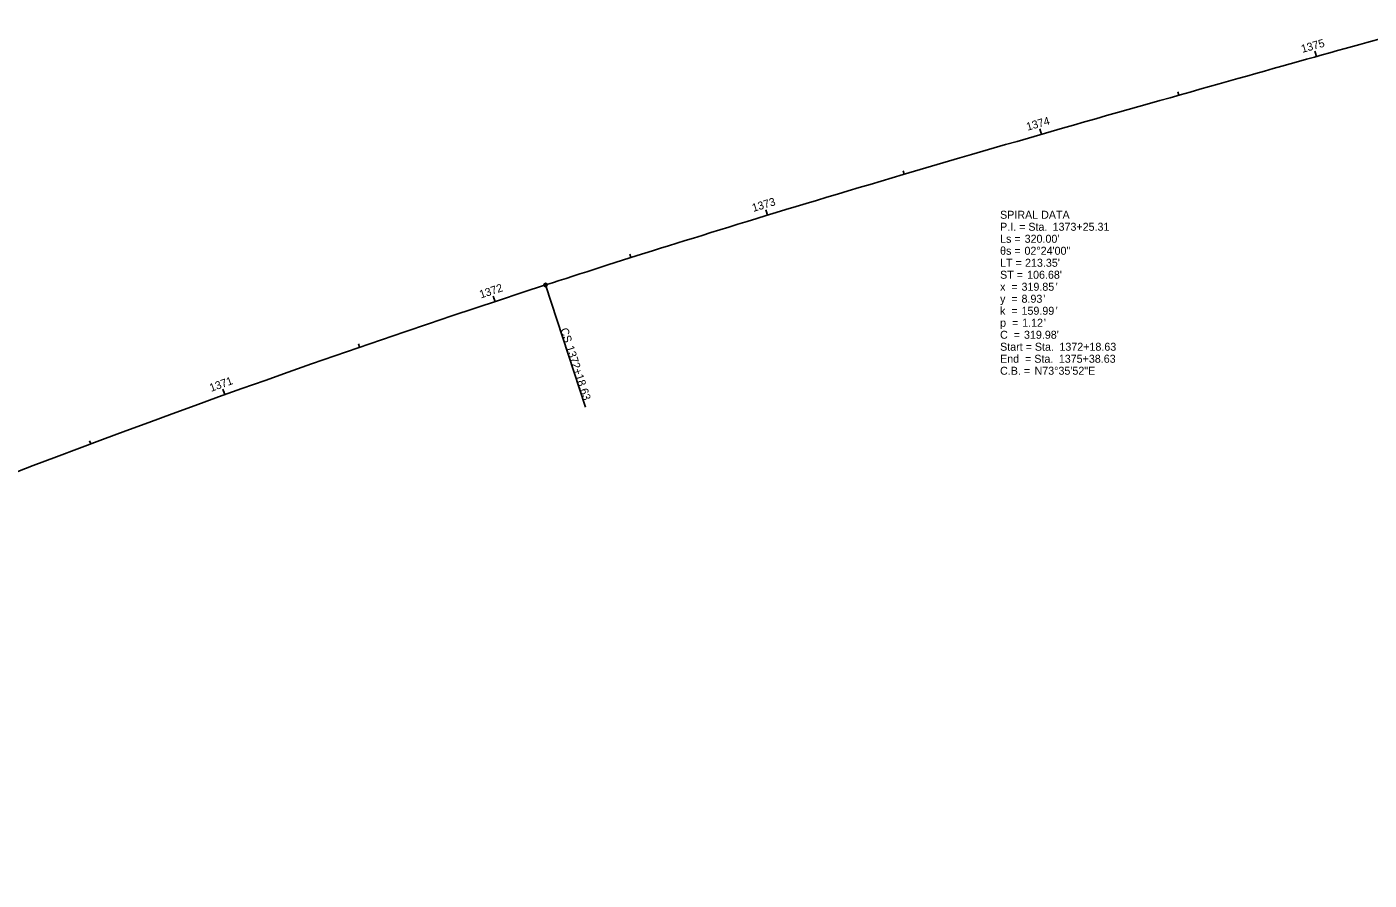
# Model space of a CAD drawing. Extents: x 153500 to 156291, y 370917 to 372075.
# Drawn here: x 154876 to 155345.7, y 371473.6 to 371772.3 of the extents above; entities that cross this region are included whole.
import ezdxf

# ---------------------------------------------------------------- set-up
doc = ezdxf.new("R2010")
doc.units = 0
for name, color, linetype in [('Default', 7, 'Continuous'), ('GE_X_Alignment', 7, 'Continuous'), ('GE_X_Alignment_1000_Curve_Data', 7, 'Continuous'), ('GE_X_Alignment_1000_Stations', 7, 'Continuous'), ('GE_X_Alignment_100_Curve_Data', 7, 'Continuous'), ('GE_X_Alignment_100_Stations', 7, 'Continuous'), ('GE_X_Alignment_500_Curve_Data', 7, 'Continuous'), ('GE_X_Alignment_500_Stations', 7, 'Continuous')]:
    doc.layers.add(name, color=color, linetype=linetype)

msp = doc.modelspace()

# ---------------------------------------------------------------- linework, layer by layer
at = {"layer": 'Default'}
msp.add_arc((156238, 368049.26), 3819.72, 108.0022, 116.29803, dxfattribs=at)
msp.add_open_spline([(155057.5, 371681.99), (155070.18, 371686.11), (155095.59, 371694.22), (155146.54, 371709.97), (155210.47, 371728.9), (155274.58, 371747.17), (155325.93, 371761.58), (155351.61, 371768.75), (155364.46, 371772.34)], degree=3, dxfattribs=at)
at = {"layer": 'GE_X_Alignment'}
msp.add_arc((156238, 368049.26), 3819.72, 108.0022, 116.29803, dxfattribs=at)
msp.add_open_spline([(155057.5, 371681.99), (155070.18, 371686.11), (155095.59, 371694.22), (155146.54, 371709.97), (155210.47, 371728.9), (155274.58, 371747.17), (155325.93, 371761.58), (155351.61, 371768.75), (155364.46, 371772.34)], degree=3, dxfattribs=at)
at = {"layer": 'GE_X_Alignment_1000_Stations'}
for p, q in [((155327.26, 371761.94), (155326.93, 371763.1)), ((155057.5, 371681.99), (155071.41, 371639.19))]:
    msp.add_line(p, q, dxfattribs=at)
msp.add_circle((155057.5, 371681.99), 0.6, dxfattribs=at)
at = {"layer": 'GE_X_Alignment_100_Stations'}
for p, q in [((155327.26, 371761.94), (155326.72, 371763.87)), ((155279.12, 371748.41), (155278.8, 371749.57)), ((155231.04, 371734.71), (155230.48, 371736.63)), ((155183.03, 371720.73), (155182.69, 371721.88)), ((155135.13, 371706.38), (155134.55, 371708.29)), ((155087.38, 371691.56), (155087.02, 371692.71)), ((155057.5, 371681.99), (155071.41, 371639.19)), ((155039.8, 371676.19), (155039.18, 371678.09)), ((154992.43, 371660.19), (154992.04, 371661.33)), ((154945.27, 371643.58), (154944.6, 371645.46)), ((154898.33, 371626.35), (154897.91, 371627.47))]:
    msp.add_line(p, q, dxfattribs=at)
msp.add_circle((155057.5, 371681.99), 0.6, dxfattribs=at)
at = {"layer": 'GE_X_Alignment_500_Stations'}
for p, q in [((155327.26, 371761.94), (155326.72, 371763.87)), ((155231.04, 371734.71), (155230.71, 371735.86)), ((155135.13, 371706.38), (155134.78, 371707.53)), ((155057.5, 371681.99), (155071.41, 371639.19)), ((155039.8, 371676.19), (155039.43, 371677.33)), ((154945.27, 371643.58), (154944.87, 371644.71))]:
    msp.add_line(p, q, dxfattribs=at)
msp.add_circle((155057.5, 371681.99), 0.6, dxfattribs=at)

# ---------------------------------------------------------------- texts
at = {"layer": 'GE_X_Alignment_1000_Curve_Data'}
for s, p in [('SPIRAL DATA', (155216.56, 371705.16)), ('P.I. = Sta. ', (155216.56, 371700.96)), ('1373+25.31', (155234.93, 371700.96)), ('Ls = ', (155216.56, 371696.76)), ("320.00'", (155225.15, 371696.76)), ('θs = ', (155216.56, 371692.56)), ('02°24\'00"', (155225.09, 371692.56)), ('LT = ', (155216.56, 371688.36)), ("213.35'", (155225.29, 371688.36)), ('ST = ', (155216.56, 371684.16)), ("106.68'", (155226.02, 371684.16)), ('x  = ', (155216.56, 371679.96)), ('319.85', (155224.06, 371679.96)), ("'", (155236.02, 371679.96)), ('y  = ', (155216.56, 371675.76)), ('k  = ', (155216.56, 371671.56)), ('8.93', (155224.06, 371675.76)), ('159.99', (155224.06, 371671.56)), ("'", (155231.67, 371675.76)), ("'", (155236.02, 371671.56)), ('p  = ', (155216.56, 371667.36)), ('1.12', (155224.28, 371667.36)), ("'", (155231.89, 371667.36)), ('C  = ', (155216.56, 371663.16)), ("319.98'", (155224.93, 371663.16)), ('Start = Sta. ', (155216.56, 371658.96)), ('1372+18.63', (155237.32, 371658.96)), ('End  = Sta. ', (155216.56, 371654.76)), ('1375+38.63', (155237.11, 371654.76)), ('C.B. = ', (155216.56, 371650.56)), ('N73°35\'52"E', (155228.62, 371650.56))]:
    msp.add_text(s, height=2.8, dxfattribs=at).set_placement(p)
at = {"layer": 'GE_X_Alignment_1000_Stations'}
for s, p in [('CS', (155062.6, 371666.45)), ('1372+18.63', (155064.62, 371660.25))]:
    msp.add_text(s, height=2.8, rotation=288.0022, dxfattribs=at).set_placement(p)
at = {"layer": 'GE_X_Alignment_100_Curve_Data'}
for s, p in [('SPIRAL DATA', (155216.56, 371705.16)), ('P.I. = Sta. ', (155216.56, 371700.96)), ('1373+25.31', (155234.93, 371700.96)), ('Ls = ', (155216.56, 371696.76)), ("320.00'", (155225.15, 371696.76)), ('θs = ', (155216.56, 371692.56)), ('02°24\'00"', (155225.09, 371692.56)), ('LT = ', (155216.56, 371688.36)), ("213.35'", (155225.29, 371688.36)), ('ST = ', (155216.56, 371684.16)), ("106.68'", (155226.02, 371684.16)), ('x  = ', (155216.56, 371679.96)), ('319.85', (155224.06, 371679.96)), ("'", (155236.02, 371679.96)), ('y  = ', (155216.56, 371675.76)), ('k  = ', (155216.56, 371671.56)), ('8.93', (155224.06, 371675.76)), ('159.99', (155224.06, 371671.56)), ("'", (155231.67, 371675.76)), ("'", (155236.02, 371671.56)), ('p  = ', (155216.56, 371667.36)), ('1.12', (155224.28, 371667.36)), ("'", (155231.89, 371667.36)), ('C  = ', (155216.56, 371663.16)), ("319.98'", (155224.93, 371663.16)), ('Start = Sta. ', (155216.56, 371658.96)), ('1372+18.63', (155237.32, 371658.96)), ('End  = Sta. ', (155216.56, 371654.76)), ('1375+38.63', (155237.11, 371654.76)), ('C.B. = ', (155216.56, 371650.56)), ('N73°35\'52"E', (155228.62, 371650.56))]:
    msp.add_text(s, height=2.8, dxfattribs=at).set_placement(p)
at = {"layer": 'GE_X_Alignment_100_Stations'}
for s, rotation, p in [('1375', 15.6372, (155322.35, 371763.22)), ('1374', 16.0526, (155226.18, 371735.96)), ('1373', 16.9368, (155130.23, 371707.55)), ('1372', 18.2816, (155034.86, 371677.24)), ('CS', 288.0022, (155062.6, 371666.45)), ('1372+18.63', 288.0022, (155064.62, 371660.25)), ('1371', 19.7816, (154940.46, 371644.55))]:
    msp.add_text(s, height=2.8, rotation=rotation, dxfattribs=at).set_placement(p)
at = {"layer": 'GE_X_Alignment_500_Curve_Data'}
for s, p in [('SPIRAL DATA', (155216.56, 371705.16)), ('P.I. = Sta. ', (155216.56, 371700.96)), ('1373+25.31', (155234.93, 371700.96)), ('Ls = ', (155216.56, 371696.76)), ("320.00'", (155225.15, 371696.76)), ('θs = ', (155216.56, 371692.56)), ('02°24\'00"', (155225.09, 371692.56)), ('LT = ', (155216.56, 371688.36)), ("213.35'", (155225.29, 371688.36)), ('ST = ', (155216.56, 371684.16)), ("106.68'", (155226.02, 371684.16)), ('x  = ', (155216.56, 371679.96)), ('319.85', (155224.06, 371679.96)), ("'", (155236.02, 371679.96)), ('y  = ', (155216.56, 371675.76)), ('k  = ', (155216.56, 371671.56)), ('8.93', (155224.06, 371675.76)), ('159.99', (155224.06, 371671.56)), ("'", (155231.67, 371675.76)), ("'", (155236.02, 371671.56)), ('p  = ', (155216.56, 371667.36)), ('1.12', (155224.28, 371667.36)), ("'", (155231.89, 371667.36)), ('C  = ', (155216.56, 371663.16)), ("319.98'", (155224.93, 371663.16)), ('Start = Sta. ', (155216.56, 371658.96)), ('1372+18.63', (155237.32, 371658.96)), ('End  = Sta. ', (155216.56, 371654.76)), ('1375+38.63', (155237.11, 371654.76)), ('C.B. = ', (155216.56, 371650.56)), ('N73°35\'52"E', (155228.62, 371650.56))]:
    msp.add_text(s, height=2.8, dxfattribs=at).set_placement(p)
at = {"layer": 'GE_X_Alignment_500_Stations'}
for s, rotation, p in [('1375', 15.6372, (155322.35, 371763.22)), ('CS', 288.0022, (155062.6, 371666.45)), ('1372+18.63', 288.0022, (155064.62, 371660.25))]:
    msp.add_text(s, height=2.8, rotation=rotation, dxfattribs=at).set_placement(p)

doc.saveas('drawing.dxf')
